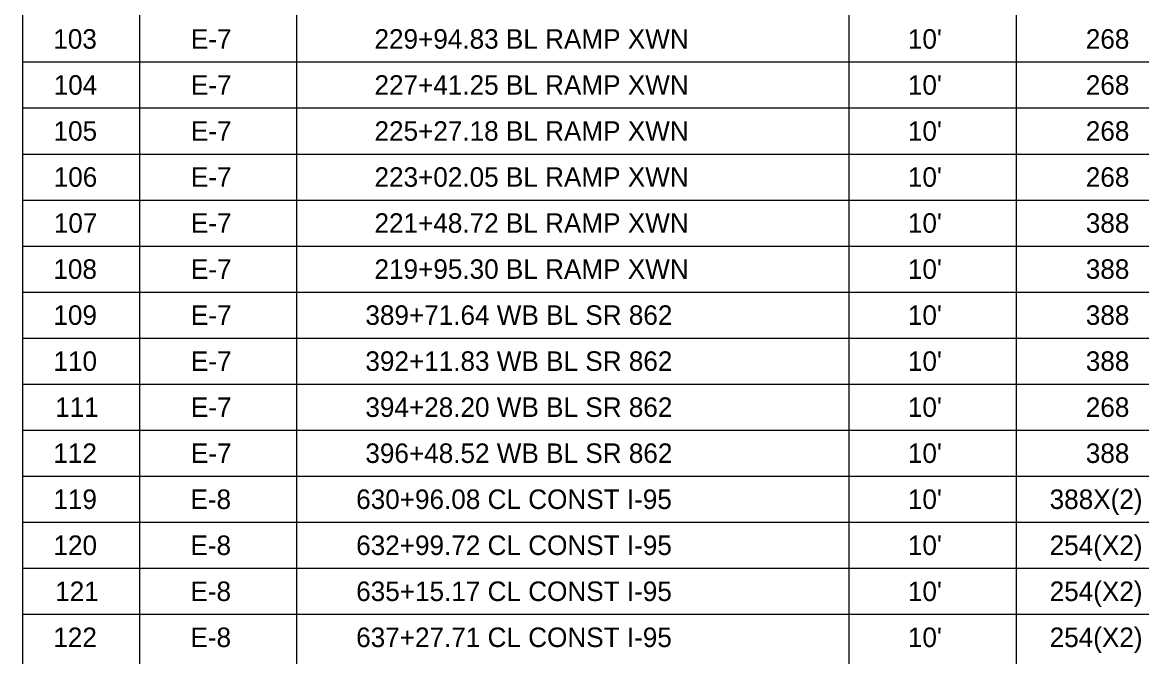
# Model space of a CAD drawing. Extents: x -818.1 to -802.4, y -2221.2 to -2187.7.
# Drawn here: x -817.208 to -813.196, y -2204.081 to -2201.807 of the extents above; entities that cross this region are included whole.
import ezdxf

# ---------------------------------------------------------------- set-up
doc = ezdxf.new("R2010")
doc.units = 0
for name, color, linetype in [('SumBoxBorder_dp', 7, 'Continuous'), ('SumBoxLines_dp', 7, 'Continuous'), ('SumBoxLinesMin_dp', 7, 'Continuous'), ('TextLabel', 7, 'Continuous')]:
    doc.layers.add(name, color=color, linetype=linetype)

msp = doc.modelspace()

# ---------------------------------------------------------------- linework, layer by layer
at = {"layer": 'SumBoxBorder_dp'}
msp.add_line((-817.2082, -2199.4742), (-817.2082, -2206.2692), dxfattribs=at)
at = {"layer": 'SumBoxLines_dp'}
for p, q in [((-816.7882, -2199.8042), (-816.7882, -2206.2692)), ((-816.7882, -2199.8042), (-816.7882, -2206.2692)), ((-816.2257, -2199.8042), (-816.2257, -2206.2692)), ((-816.2257, -2199.8042), (-816.2257, -2206.2692)), ((-814.2457, -2199.8042), (-814.2457, -2206.2692)), ((-814.2457, -2199.8042), (-814.2457, -2206.2692)), ((-813.6457, -2199.8042), (-813.6457, -2206.2692)), ((-813.6457, -2199.8042), (-813.6457, -2206.2692))]:
    msp.add_line(p, q, dxfattribs=at)
at = {"layer": 'SumBoxLinesMin_dp'}
for p, q in [((-817.2082, -2201.9492), (-809.6857, -2201.9492)), ((-817.2082, -2201.9492), (-809.6857, -2201.9492)), ((-817.2082, -2202.1142), (-809.6857, -2202.1142)), ((-817.2082, -2202.1142), (-809.6857, -2202.1142)), ((-817.2082, -2202.2792), (-809.6857, -2202.2792)), ((-817.2082, -2202.2792), (-809.6857, -2202.2792)), ((-817.2082, -2202.4442), (-809.6857, -2202.4442)), ((-817.2082, -2202.4442), (-809.6857, -2202.4442)), ((-817.2082, -2202.6092), (-809.6857, -2202.6092)), ((-817.2082, -2202.6092), (-809.6857, -2202.6092)), ((-817.2082, -2202.7742), (-809.6857, -2202.7742)), ((-817.2082, -2202.7742), (-809.6857, -2202.7742)), ((-817.2082, -2202.9392), (-809.6857, -2202.9392)), ((-817.2082, -2202.9392), (-809.6857, -2202.9392)), ((-817.2082, -2203.1042), (-809.6857, -2203.1042)), ((-817.2082, -2203.1042), (-809.6857, -2203.1042)), ((-817.2082, -2203.2692), (-809.6857, -2203.2692)), ((-817.2082, -2203.2692), (-809.6857, -2203.2692)), ((-817.2082, -2203.4342), (-809.6857, -2203.4342)), ((-817.2082, -2203.4342), (-809.6857, -2203.4342)), ((-817.2082, -2203.5992), (-809.6857, -2203.5992)), ((-817.2082, -2203.5992), (-809.6857, -2203.5992)), ((-817.2082, -2203.7642), (-809.6857, -2203.7642)), ((-817.2082, -2203.7642), (-809.6857, -2203.7642)), ((-817.2082, -2203.9292), (-809.6857, -2203.9292)), ((-817.2082, -2203.9292), (-809.6857, -2203.9292))]:
    msp.add_line(p, q, dxfattribs=at)

# ---------------------------------------------------------------- texts
at = {"layer": 'TextLabel'}
for s, p in [('103', (-817.0974, -2201.9017)), ('E-7', (-816.6041, -2201.9017)), ('229+94.83 BL RAMP XWN', (-815.9458, -2201.9017)), ("10'", (-814.0336, -2201.9017)), ('268', (-813.3958, -2201.9017)), ('104', (-817.096, -2202.0667)), ('E-7', (-816.6041, -2202.0667)), ('227+41.25 BL RAMP XWN', (-815.9458, -2202.0667)), ("10'", (-814.0336, -2202.0667)), ('268', (-813.3958, -2202.0667)), ('105', (-817.0965, -2202.2317)), ('E-7', (-816.6041, -2202.2317)), ('225+27.18 BL RAMP XWN', (-815.9458, -2202.2317)), ("10'", (-814.0336, -2202.2317)), ('268', (-813.3958, -2202.2317)), ('106', (-817.0959, -2202.3967)), ('E-7', (-816.6041, -2202.3967)), ('223+02.05 BL RAMP XWN', (-815.9458, -2202.3967)), ("10'", (-814.0336, -2202.3967)), ('268', (-813.3958, -2202.3967)), ('107', (-817.0953, -2202.5617)), ('E-7', (-816.6041, -2202.5617)), ('221+48.72 BL RAMP XWN', (-815.9458, -2202.5617)), ("10'", (-814.0336, -2202.5617)), ('388', (-813.3958, -2202.5617)), ('108', (-817.0971, -2202.7267)), ('E-7', (-816.6041, -2202.7267)), ('219+95.30 BL RAMP XWN', (-815.9458, -2202.7267)), ("10'", (-814.0336, -2202.7267)), ('388', (-813.3958, -2202.7267)), ('109', (-817.097, -2202.8917)), ('E-7', (-816.6041, -2202.8917)), ('389+71.64 WB BL SR 862', (-815.9785, -2202.8917)), ("10'", (-814.0336, -2202.8917)), ('388', (-813.3958, -2202.8917)), ('110', (-817.0968, -2203.0567)), ('E-7', (-816.6041, -2203.0567)), ('392+11.83 WB BL SR 862', (-815.9785, -2203.0567)), ("10'", (-814.0336, -2203.0567)), ('388', (-813.3958, -2203.0567)), ('111', (-817.0906, -2203.2217)), ('E-7', (-816.6041, -2203.2217)), ('394+28.20 WB BL SR 862', (-815.9785, -2203.2217)), ("10'", (-814.0336, -2203.2217)), ('268', (-813.3958, -2203.2217)), ('112', (-817.0973, -2203.3867)), ('E-7', (-816.6041, -2203.3867)), ('396+48.52 WB BL SR 862', (-815.9785, -2203.3867)), ("10'", (-814.0336, -2203.3867)), ('388', (-813.3958, -2203.3867)), ('119', (-817.097, -2203.5517)), ('E-8', (-816.6058, -2203.5517)), ('630+96.08 CL CONST I-95', (-816.0115, -2203.5517)), ("10'", (-814.0336, -2203.5517)), ('388X(2)', (-813.5254, -2203.5517)), ('120', (-817.0968, -2203.7167)), ('E-8', (-816.6058, -2203.7167)), ('632+99.72 CL CONST I-95', (-816.0115, -2203.7167)), ("10'", (-814.0336, -2203.7167)), ('254(X2)', (-813.5254, -2203.7167)), ('121', (-817.0906, -2203.8817)), ('E-8', (-816.6058, -2203.8817)), ('635+15.17 CL CONST I-95', (-816.0115, -2203.8817)), ("10'", (-814.0336, -2203.8817)), ('254(X2)', (-813.5254, -2203.8817)), ('122', (-817.0973, -2204.0467)), ('E-8', (-816.6058, -2204.0467)), ('637+27.71 CL CONST I-95', (-816.0115, -2204.0467)), ("10'", (-814.0336, -2204.0467)), ('254(X2)', (-813.5254, -2204.0467))]:
    msp.add_text(s, height=0.07, dxfattribs=at).set_placement(p)

doc.saveas('drawing.dxf')
